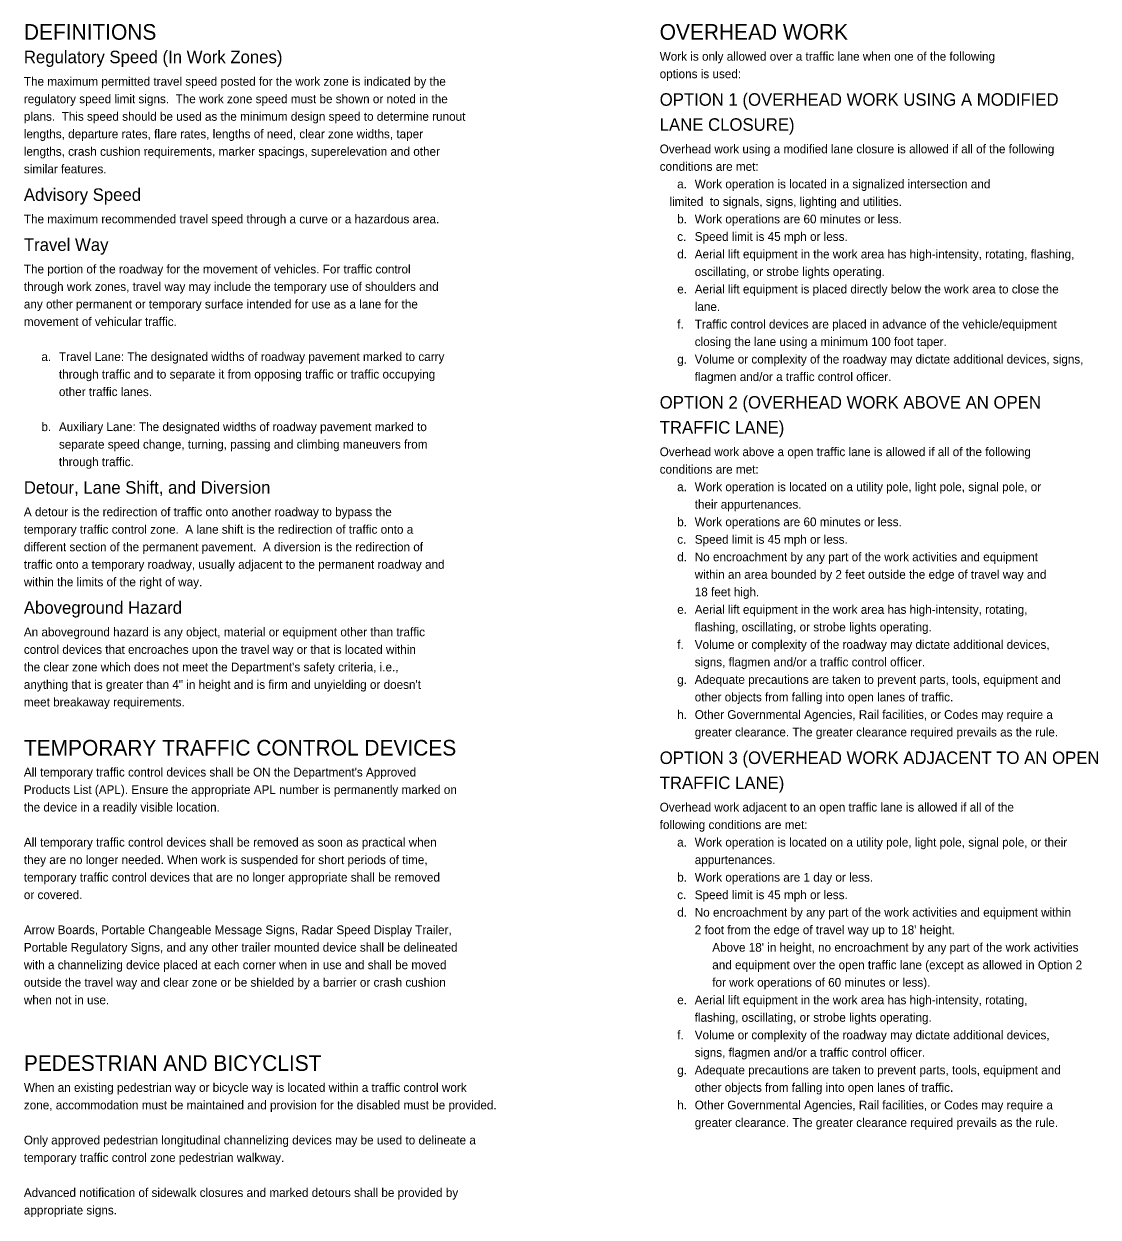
# Model space of a CAD drawing. Extents: x 10044 to 10735, y 10038 to 10515.
# Drawn here: x 10044 to 10473.2, y 10038.1 to 10514.8 of the extents above; entities that cross this region are included whole.
import ezdxf

# ---------------------------------------------------------------- set-up
doc = ezdxf.new("R2010")
doc.units = 0
doc.layers.add('SupstrConc', color=7, linetype='Continuous')

msp = doc.modelspace()

# ---------------------------------------------------------------- texts
at = {"layer": 'SupstrConc'}
for s, height, p in [('DEFINITIONS', 6.25, (10044.03, 10508.5)), ('OVERHEAD WORK', 6.25, (10298.06, 10508.5)), ('Regulatory Speed (In Work Zones)', 5, (10044.03, 10499.12)), ('Work is only allowed over a traffic lane when one of the following ', 3.5, (10298.06, 10500.12)), ('The maximum permitted travel speed posted for the work zone is indicated by the ', 3.5, (10044.03, 10490.12)), ('options is used:', 3.5, (10298.06, 10493.12)), ('regulatory speed limit signs.  The work zone speed must be shown or noted in the ', 3.5, (10044.03, 10483.12)), ('OPTION 1 (OVERHEAD WORK USING A MODIFIED ', 5, (10298.06, 10482.12)), ('plans.  This speed should be used as the minimum design speed to determine runout ', 3.5, (10044.03, 10476.12)), ('LANE CLOSURE)', 5, (10298.06, 10472.12)), ('lengths, departure rates, flare rates, lengths of need, clear zone widths, taper ', 3.5, (10044.03, 10469.12)), ('lengths, crash cushion requirements, marker spacings, superelevation and other ', 3.5, (10044.03, 10462.12)), ('Overhead work using a modified lane closure is allowed if all of the following ', 3.5, (10298.06, 10463.12)), ('similar features.  ', 3.5, (10044.03, 10455.12)), ('conditions are met:', 3.5, (10298.06, 10456.12)), ('a.', 3.5, (10305.06, 10449.12)), ('Work operation is located in a signalized intersection and ', 3.5, (10312.06, 10449.12)), ('Advisory Speed', 5, (10044.03, 10444.12)), ('   limited  to signals, signs, lighting and utilities.', 3.5, (10298.06, 10442.12)), ('The maximum recommended travel speed through a curve or a hazardous area. ', 3.5, (10044.03, 10435.12)), ('b.', 3.5, (10305.06, 10435.12)), ('Work operations are 60 minutes or less.', 3.5, (10312.06, 10435.12)), ('Travel Way', 5, (10044.03, 10424.12)), ('c.', 3.5, (10305.06, 10428.12)), ('Speed limit is 45 mph or less.', 3.5, (10312.06, 10428.12)), ('d.', 3.5, (10305.06, 10421.12)), ('Aerial lift equipment in the work area has high-intensity, rotating, flashing, ', 3.5, (10312.06, 10421.12)), ('The portion of the roadway for the movement of vehicles. For traffic control ', 3.5, (10044.03, 10415.12)), ('oscillating, or strobe lights operating.', 3.5, (10312.06, 10414.12)), ('through work zones, travel way may include the temporary use of shoulders and ', 3.5, (10044.03, 10408.12)), ('e.', 3.5, (10305.06, 10407.12)), ('Aerial lift equipment is placed directly below the work area to close the ', 3.5, (10312.06, 10407.12)), ('any other permanent or temporary surface intended for use as a lane for the ', 3.5, (10044.03, 10401.12)), ('lane.', 3.5, (10312.06, 10400.12)), ('movement of vehicular traffic.', 3.5, (10044.03, 10394.12)), ('f.', 3.5, (10305.06, 10393.12)), ('Traffic control devices are placed in advance of the vehicle/equipment ', 3.5, (10312.06, 10393.12)), ('closing the lane using a minimum 100 foot taper.', 3.5, (10312.06, 10386.12)), ('a.', 3.5, (10051.03, 10380.12)), ('Travel Lane: The designated widths of roadway pavement marked to carry ', 3.5, (10058.03, 10380.12)), ('g.', 3.5, (10305.06, 10379.12)), ('Volume or complexity of the roadway may dictate additional devices, signs, ', 3.5, (10312.06, 10379.12)), ('through traffic and to separate it from opposing traffic or traffic occupying ', 3.5, (10058.03, 10373.12)), ('flagmen and/or a traffic control officer.', 3.5, (10312.06, 10372.12)), ('other traffic lanes.', 3.5, (10058.03, 10366.12)), ('OPTION 2 (OVERHEAD WORK ABOVE AN OPEN ', 5, (10298.06, 10361.12)), ('b.', 3.5, (10051.03, 10352.12)), ('Auxiliary Lane: The designated widths of roadway pavement marked to ', 3.5, (10058.03, 10352.12)), ('TRAFFIC LANE)', 5, (10298.06, 10351.12)), ('separate speed change, turning, passing and climbing maneuvers from ', 3.5, (10058.03, 10345.12)), ('through traffic.', 3.5, (10058.03, 10338.12)), ('Overhead work above a open traffic lane is allowed if all of the following ', 3.5, (10298.06, 10342.12)), ('conditions are met: ', 3.5, (10298.06, 10335.12)), ('Detour, Lane Shift, and Diversion', 5, (10044.03, 10327.12)), ('Work operation is located on a utility pole, light pole, signal pole, or ', 3.5, (10312.06, 10328.12)), ('a.', 3.5, (10305.06, 10328.12)), ('their appurtenances.', 3.5, (10312.06, 10321.12)), ('A detour is the redirection of traffic onto another roadway to bypass the ', 3.5, (10044.03, 10318.12)), ('b.', 3.5, (10305.06, 10314.12)), ('Work operations are 60 minutes or less.', 3.5, (10312.06, 10314.12)), ('temporary traffic control zone.  A lane shift is the redirection of traffic onto a ', 3.5, (10044.03, 10311.12)), ('c.', 3.5, (10305.06, 10307.12)), ('Speed limit is 45 mph or less.', 3.5, (10312.06, 10307.12)), ('different section of the permanent pavement.  A diversion is the redirection of ', 3.5, (10044.03, 10304.12)), ('d.', 3.5, (10305.06, 10300.12)), ('No encroachment by any part of the work activities and equipment ', 3.5, (10312.06, 10300.12)), ('traffic onto a temporary roadway, usually adjacent to the permanent roadway and ', 3.5, (10044.03, 10297.12)), ('within the limits of the right of way. ', 3.5, (10044.03, 10290.12)), ('within an area bounded by 2 feet outside the edge of travel way and ', 3.5, (10312.06, 10293.12)), ('18 feet high.', 3.5, (10312.06, 10286.12)), ('Aboveground Hazard ', 5, (10044.03, 10279.12)), ('e.', 3.5, (10305.06, 10279.12)), ('Aerial lift equipment in the work area has high-intensity, rotating, ', 3.5, (10312.06, 10279.12)), ('flashing, oscillating, or strobe lights operating.', 3.5, (10312.06, 10272.12)), ('An aboveground hazard is any object, material or equipment other than traffic ', 3.5, (10044.03, 10270.12)), ('control devices that encroaches upon the travel way or that is located within ', 3.5, (10044.03, 10263.12)), ('f.', 3.5, (10305.06, 10265.12)), ('Volume or complexity of the roadway may dictate additional devices, ', 3.5, (10312.06, 10265.12)), ('signs, flagmen and/or a traffic control officer.', 3.5, (10312.06, 10258.12)), ("the clear zone which does not meet the Department's safety criteria, i.e., ", 3.5, (10044.03, 10256.12)), ('anything that is greater than 4" in height and is firm and unyielding or doesn\'t ', 3.5, (10044.03, 10249.12)), ('g.', 3.5, (10305.06, 10251.12)), ('Adequate precautions are taken to prevent parts, tools, equipment and ', 3.5, (10312.06, 10251.12)), ('other objects from falling into open lanes of traffic.', 3.5, (10312.06, 10244.12)), ('meet breakaway requirements. ', 3.5, (10044.03, 10242.12)), ('h.', 3.5, (10305.06, 10237.12)), ('Other Governmental Agencies, Rail facilities, or Codes may require a ', 3.5, (10312.06, 10237.12)), ('greater clearance. The greater clearance required prevails as the rule.', 3.5, (10312.06, 10230.12)), ('TEMPORARY TRAFFIC CONTROL DEVICES', 6.25, (10044.03, 10222.5)), ('OPTION 3 (OVERHEAD WORK ADJACENT TO AN OPEN ', 5, (10298.06, 10219.12)), ("All temporary traffic control devices shall be ON the Department's Approved ", 3.5, (10044.03, 10214.12)), ('TRAFFIC LANE)', 5, (10298.06, 10209.12)), ('Products List (APL). Ensure the appropriate APL number is permanently marked on ', 3.5, (10044.03, 10207.12)), ('the device in a readily visible location.', 3.5, (10044.03, 10200.12)), ('Overhead work adjacent to an open traffic lane is allowed if all of the ', 3.5, (10298.06, 10200.12)), ('following conditions are met: ', 3.5, (10298.06, 10193.12)), ('All temporary traffic control devices shall be removed as soon as practical when ', 3.5, (10044.03, 10186.12)), ('a.', 3.5, (10305.06, 10186.12)), ('Work operation is located on a utility pole, light pole, signal pole, or their ', 3.5, (10312.06, 10186.12)), ('they are no longer needed. When work is suspended for short periods of time, ', 3.5, (10044.03, 10179.12)), ('appurtenances.', 3.5, (10312.06, 10179.12)), ('temporary traffic control devices that are no longer appropriate shall be removed ', 3.5, (10044.03, 10172.12)), ('b.', 3.5, (10305.06, 10172.12)), ('Work operations are 1 day or less.', 3.5, (10312.06, 10172.12)), ('or covered.', 3.5, (10044.03, 10165.12)), ('c.', 3.5, (10305.06, 10165.12)), ('Speed limit is 45 mph or less.', 3.5, (10312.06, 10165.12)), ('d.', 3.5, (10305.06, 10158.12)), ('No encroachment by any part of the work activities and equipment within ', 3.5, (10312.06, 10158.12)), ('Arrow Boards, Portable Changeable Message Signs, Radar Speed Display Trailer, ', 3.5, (10044.03, 10151.12)), ("2 foot from the edge of travel way up to 18' height.", 3.5, (10312.06, 10151.12)), ('Portable Regulatory Signs, and any other trailer mounted device shall be delineated ', 3.5, (10044.03, 10144.12)), ("Above 18' in height, no encroachment by any part of the work activities ", 3.5, (10319.06, 10144.12)), ('with a channelizing device placed at each corner when in use and shall be moved ', 3.5, (10044.03, 10137.12)), ('and equipment over the open traffic lane (except as allowed in Option 2 ', 3.5, (10319.06, 10137.12)), ('outside the travel way and clear zone or be shielded by a barrier or crash cushion ', 3.5, (10044.03, 10130.12)), ('for work operations of 60 minutes or less).', 3.5, (10319.06, 10130.12)), ('when not in use.', 3.5, (10044.03, 10123.12)), ('Aerial lift equipment in the work area has high-intensity, rotating, ', 3.5, (10312.06, 10123.12)), ('e.', 3.5, (10305.06, 10123.12)), ('flashing, oscillating, or strobe lights operating.', 3.5, (10312.06, 10116.12)), ('f.', 3.5, (10305.06, 10109.12)), ('Volume or complexity of the roadway may dictate additional devices, ', 3.5, (10312.06, 10109.12)), ('PEDESTRIAN AND BICYCLIST', 6.25, (10044.03, 10096.5)), ('signs, flagmen and/or a traffic control officer.', 3.5, (10312.06, 10102.12)), ('Adequate precautions are taken to prevent parts, tools, equipment and ', 3.5, (10312.06, 10095.12)), ('g.', 3.5, (10305.06, 10095.12)), ('When an existing pedestrian way or bicycle way is located within a traffic control work ', 3.5, (10044.03, 10088.12)), ('other objects from falling into open lanes of traffic.', 3.5, (10312.06, 10088.12)), ('zone, accommodation must be maintained and provision for the disabled must be provided.', 3.5, (10044.03, 10081.12)), ('h.', 3.5, (10305.06, 10081.12)), ('Other Governmental Agencies, Rail facilities, or Codes may require a ', 3.5, (10312.06, 10081.12)), ('greater clearance. The greater clearance required prevails as the rule.', 3.5, (10312.06, 10074.12)), ('Only approved pedestrian longitudinal channelizing devices may be used to delineate a ', 3.5, (10044.03, 10067.12)), ('temporary traffic control zone pedestrian walkway.', 3.5, (10044.03, 10060.12)), ('Advanced notification of sidewalk closures and marked detours shall be provided by ', 3.5, (10044.03, 10046.12)), ('appropriate signs.', 3.5, (10044.03, 10039.12))]:
    msp.add_text(s, height=height, dxfattribs=at).set_placement(p)

doc.saveas('drawing.dxf')
